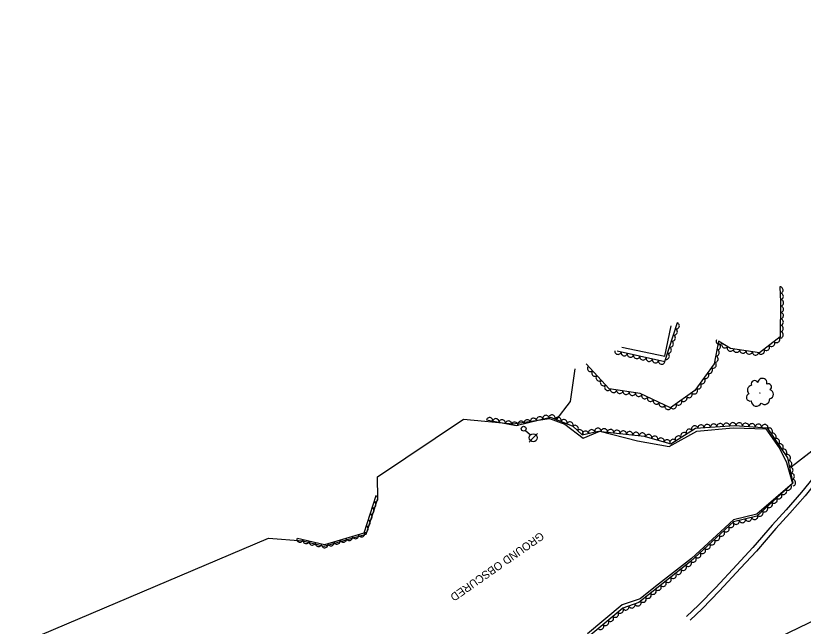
# Model space of a CAD drawing. Extents: x 1722896 to 1754269, y 648279 to 666297.
# Drawn here: x 1723621.5 to 1724113.3, y 664521.2 to 664902.6 of the extents above; entities that cross this region are included whole.
import ezdxf

# ---------------------------------------------------------------- set-up
doc = ezdxf.new("R2010")
doc.units = 0
for name, color, linetype in [('DESIGN - CENTERLINE - Proposed', 7, 'Continuous'), ('DESIGN - CENTERLINE - Proposed Text', 7, 'Continuous'), ('DESIGN - SCRATCH - User 1', 7, 'Continuous'), ('SURVEY - CENTERLINE - Preliminary', 7, 'Continuous'), ('SURVEY - CENTERLINE - Preliminary Text', 7, 'Continuous'), ('SURVEY - DTM - Breaklines', 7, 'Continuous'), ('SURVEY - VEGETATION - Features with Text', 7, 'Continuous')]:
    doc.layers.add(name, color=color, linetype=linetype)

msp = doc.modelspace()

# ---------------------------------------------------------------- linework, layer by layer
at = {"layer": 'DESIGN - CENTERLINE - Proposed'}
for points in [[(1724273.84, 664726.47), (1724258.5, 664715.78), (1724238.15, 664703.01), (1724220, 664690.73), (1724200.11, 664677.24), (1724179.59, 664664.67), (1724166.59, 664655.54), (1724151.47, 664644.92), (1724145.12, 664640.88), (1724139.39, 664634.1), (1724130.94, 664626.12), (1724122.18, 664617.34), (1724112.23, 664604.95), (1724102.71, 664594.02), (1724093.88, 664584.43), (1724081.77, 664570.4), (1724071.88, 664559.67), (1724058.71, 664545.5), (1724047.93, 664534.31), (1724040.41, 664527.26)], [(1724279.1, 664726.35), (1724260.75, 664713.56), (1724240.4, 664700.79), (1724222.25, 664688.52), (1724202.37, 664675.03), (1724181.84, 664662.46), (1724168.84, 664653.33), (1724153.72, 664642.7), (1724147.37, 664638.67), (1724141.65, 664631.89), (1724133.19, 664623.9), (1724124.43, 664615.13), (1724114.48, 664602.73), (1724104.96, 664591.81), (1724096.13, 664582.22), (1724084.02, 664568.19), (1724074.14, 664557.46), (1724060.96, 664543.28), (1724050.18, 664532.09), (1724042.67, 664525.05)]]:
    msp.add_lwpolyline(points, dxfattribs=at)
at = {"layer": 'DESIGN - CENTERLINE - Proposed Text'}
for points in [[(1724105.66, 664620.89), (1724149.56, 664654.64), (1724203.45, 664696.69), (1724251.99, 664732.46), (1724288.71, 664760.49), (1724304.32, 664767.21), (1724357.88, 664789.47), (1724411.6, 664811.84), (1724467.44, 664836.04), (1724528.61, 664861.58), (1724583.75, 664884.71), (1724626.01, 664902.56)], [(1724000.02, 664695.49), (1724026.87, 664689.9), (1724030.82, 664708.86)], [(1724105.66, 664620.89), (1724145.3, 664651.36)]]:
    msp.add_lwpolyline(points, dxfattribs=at)
at = {"layer": 'DESIGN - SCRATCH - User 1'}
msp.add_lwpolyline([(1724122.57, 664526.16), (1724091.92, 664511.24), (1724062.4, 664497.59), (1724031.5, 664483.84)], dxfattribs=at)
at = {"layer": 'SURVEY - CENTERLINE - Preliminary'}
for points in [[(1723621.54, 664509.22), (1723779.29, 664576.2), (1723800.75, 664574.58), (1723814.22, 664571.33), (1723840.37, 664578.82), (1723847.55, 664600.99), (1723847.4, 664614.53), (1723901.13, 664650.53), (1723932.15, 664647.59), (1723954.91, 664651.03), (1723964.4, 664647.44), (1723975.94, 664638.66), (1723986.23, 664643.1), (1724009.71, 664637.1), (1724029.66, 664633.44), (1724046.85, 664643.04), (1724069.49, 664645.12), (1724089.99, 664644.49)], [(1724089.99, 664644.49), (1724098.66, 664632.04), (1724102.86, 664623.56), (1724106.64, 664610.46), (1724084.34, 664591.21), (1724069.65, 664587.75), (1724043.55, 664563.45), (1724021.07, 664545.96), (1724011.52, 664538.4), (1724000.29, 664534.63), (1723978.66, 664516.56)]]:
    msp.add_lwpolyline(points, dxfattribs=at)
at = {"layer": 'SURVEY - CENTERLINE - Preliminary Text'}
msp.add_lwpolyline([(1723970.56, 664681.96), (1723967.78, 664661.56), (1723958.79, 664650)], dxfattribs=at)
at = {"layer": 'SURVEY - DTM - Breaklines'}
for p, q in [((1723939.79, 664643.59), (1723942.89, 664640.68)), ((1723944.71, 664638.97), (1723947.27, 664641.7)), ((1723944.71, 664638.97), (1723942.14, 664636.23))]:
    msp.add_line(p, q, dxfattribs=at)
for centre, radius in [((1723938.69, 664644.61), 1.5), ((1723944.71, 664638.97), 2.5)]:
    msp.add_circle(centre, radius, dxfattribs=at)
at = {"layer": 'SURVEY - VEGETATION - Features with Text'}
for points in [[(1724098.74, 664733.2), (1724099.13, 664723.8), (1724098.88, 664701.91), (1724085.93, 664692.1), (1724067.87, 664694.78), (1724060.42, 664699.36), (1724057.63, 664685.15), (1724045.59, 664668.4), (1724030.44, 664657.73), (1724011.39, 664666.52), (1723991.99, 664669.52), (1723977.75, 664685.19)], [(1724034.66, 664710.74), (1724026.68, 664686.48)], [(1724026.85, 664686.33), (1723996.99, 664693.03)], [(1723915.45, 664650.08), (1723934.03, 664646.67), (1723955.45, 664651.8), (1723969.43, 664646.19), (1723975.31, 664640.73), (1723985.16, 664643.12), (1724013.99, 664639.96), (1724030.5, 664635.17), (1724046.04, 664644.88), (1724070.58, 664646.61), (1724090.72, 664645.25), (1724103.45, 664626.42), (1724106.71, 664610.67), (1724084.28, 664590.07), (1724069.79, 664586.34), (1724042.87, 664561.57), (1724010.68, 664535.98), (1724000.66, 664532.6), (1723979.33, 664514.81)], [(1723846.44, 664602.75), (1723838.91, 664579.36), (1723814.27, 664572.04), (1723797.5, 664575.94)]]:
    msp.add_lwpolyline(points, dxfattribs=at)
msp.add_circle((1724086.22, 664667), 0.0997, dxfattribs=at)
for centre, radius, start, end in [((1724087.8, 664673.22), 2.85, 341.8001, 175.2198), ((1724081.49, 664668.72), 3.07, 99.7058, 226.5515), ((1724082.98, 664672.56), 2.17, 24.4188, 201.7379), ((1724091.5, 664670.64), 1.96, 301.7794, 120.5251), ((1724080.18, 664664.25), 2.38, 109.8647, 284.865), ((1724091.87, 664666.19), 2.86, 279.6633, 76.4522), ((1724084.03, 664661.92), 3.23, 179.6118, 335.4503), ((1724089.12, 664663.03), 3.25, 228.716, 6.2402)]:
    msp.add_arc(centre, radius, start, end, dxfattribs=at)
for centre, major_axis in [((1724098.82, 664731.2), (0.08, -2)), ((1724098.99, 664727.21), (0.08, -2)), ((1724099.12, 664723.21), (-0.02, -2)), ((1724099.08, 664719.21), (-0.02, -2)), ((1724099.03, 664715.21), (-0.02, -2)), ((1724034.04, 664708.84), (-0.62, -1.9)), ((1724098.98, 664711.21), (-0.02, -2)), ((1724032.79, 664705.04), (-0.62, -1.9)), ((1724098.94, 664707.21), (-0.02, -2)), ((1724031.54, 664701.24), (-0.62, -1.9)), ((1724096.73, 664700.28), (-1.59, -1.21)), ((1724098.89, 664703.21), (-0.02, -2)), ((1724029.04, 664693.64), (-0.62, -1.9)), ((1724030.29, 664697.44), (-0.62, -1.9)), ((1724060.89, 664699.07), (-1.7, 1.05)), ((1724059.76, 664695.98), (-0.39, -1.96)), ((1724064.3, 664696.97), (-1.7, 1.05)), ((1724067.71, 664694.88), (-1.7, 1.05)), ((1724090.36, 664695.45), (-1.59, -1.21)), ((1724093.54, 664697.86), (-1.59, -1.21)), ((1723997.57, 664692.9), (-1.95, 0.44)), ((1724001.48, 664692.02), (-1.95, 0.44)), ((1724005.38, 664691.15), (-1.95, 0.44)), ((1724009.28, 664690.27), (-1.95, 0.44)), ((1724027.79, 664689.84), (-0.62, -1.9)), ((1724058.99, 664692.05), (-0.39, -1.96)), ((1724071.64, 664694.22), (-1.98, 0.29)), ((1724075.59, 664693.63), (-1.98, 0.29)), ((1724079.55, 664693.04), (-1.98, 0.29)), ((1724083.51, 664692.46), (-1.98, 0.29)), ((1724087.17, 664693.03), (-1.59, -1.21)), ((1724013.19, 664689.4), (-1.95, 0.44)), ((1724017.09, 664688.52), (-1.95, 0.44)), ((1724020.99, 664687.65), (-1.95, 0.44)), ((1724024.89, 664686.77), (-1.95, 0.44)), ((1724057.07, 664684.37), (-1.17, -1.62)), ((1724058.22, 664688.13), (-0.39, -1.96)), ((1723980.42, 664682.25), (-1.35, 1.48)), ((1723983.11, 664679.29), (-1.35, 1.48)), ((1724054.73, 664681.12), (-1.17, -1.62)), ((1723985.8, 664676.33), (-1.35, 1.48)), ((1724050.06, 664674.62), (-1.17, -1.62)), ((1724052.4, 664677.87), (-1.17, -1.62)), ((1723988.49, 664673.37), (-1.35, 1.48)), ((1723991.18, 664670.41), (-1.35, 1.48)), ((1724047.73, 664671.37), (-1.17, -1.62)), ((1723994.76, 664669.09), (-1.98, 0.31)), ((1723998.71, 664668.48), (-1.98, 0.31)), ((1724002.66, 664667.87), (-1.98, 0.31)), ((1724006.62, 664667.26), (-1.98, 0.31)), ((1724010.57, 664666.65), (-1.98, 0.31)), ((1724014.27, 664665.19), (-1.82, 0.84)), ((1724042.05, 664665.9), (-1.64, -1.15)), ((1724045.32, 664668.21), (-1.64, -1.15)), ((1724017.9, 664663.52), (-1.82, 0.84)), ((1724021.53, 664661.84), (-1.82, 0.84)), ((1724035.5, 664661.3), (-1.64, -1.15)), ((1724038.77, 664663.6), (-1.64, -1.15)), ((1724025.17, 664660.17), (-1.82, 0.84)), ((1724028.8, 664658.49), (-1.82, 0.84)), ((1724032.23, 664659), (-1.64, -1.15)), ((1723917.42, 664649.72), (1.97, -0.36)), ((1723944.84, 664649.26), (1.95, 0.47)), ((1723948.73, 664650.19), (1.95, 0.47)), ((1723952.62, 664651.12), (1.95, 0.47)), ((1723956.46, 664651.39), (1.86, -0.74)), ((1723960.17, 664649.9), (1.86, -0.74)), ((1723921.35, 664649), (1.97, -0.36)), ((1723925.29, 664648.28), (1.97, -0.36)), ((1723929.22, 664647.55), (1.97, -0.36)), ((1723933.16, 664646.83), (1.97, -0.36)), ((1723937.06, 664647.4), (1.95, 0.47)), ((1723940.95, 664648.33), (1.95, 0.47)), ((1723963.88, 664648.42), (1.86, -0.74)), ((1723967.6, 664646.93), (1.86, -0.74)), ((1723970.91, 664644.82), (1.47, -1.36)), ((1724045.49, 664644.54), (1.7, 1.06)), ((1724049.38, 664645.11), (2, 0.14)), ((1724053.37, 664645.39), (2, 0.14)), ((1724057.36, 664645.68), (2, 0.14)), ((1724061.35, 664645.96), (2, 0.14)), ((1724065.34, 664646.24), (2, 0.14)), ((1724069.33, 664646.52), (2, 0.14)), ((1724073.32, 664646.42), (2, -0.13)), ((1724077.32, 664646.15), (2, -0.13)), ((1724081.31, 664645.88), (2, -0.13)), ((1724085.3, 664645.62), (2, -0.13)), ((1724089.29, 664645.35), (2, -0.13)), ((1723973.85, 664642.09), (1.47, -1.36)), ((1723977.26, 664641.21), (1.94, 0.47)), ((1723981.14, 664642.15), (1.94, 0.47)), ((1723985.03, 664643.09), (1.94, 0.47)), ((1723989, 664642.7), (1.99, -0.22)), ((1723992.98, 664642.27), (1.99, -0.22)), ((1723996.96, 664641.83), (1.99, -0.22)), ((1724000.93, 664641.39), (1.99, -0.22)), ((1724004.91, 664640.96), (1.99, -0.22)), ((1724008.88, 664640.52), (1.99, -0.22)), ((1724012.86, 664640.09), (1.99, -0.22)), ((1724038.7, 664640.3), (1.7, 1.06)), ((1724042.1, 664642.42), (1.7, 1.06)), ((1724092.16, 664643.12), (1.12, -1.66)), ((1724094.4, 664639.81), (1.12, -1.66)), ((1724016.74, 664639.16), (1.92, -0.56)), ((1724020.58, 664638.05), (1.92, -0.56)), ((1724024.42, 664636.93), (1.92, -0.56)), ((1724028.27, 664635.82), (1.92, -0.56)), ((1724031.92, 664636.06), (1.7, 1.06)), ((1724035.31, 664638.18), (1.7, 1.06)), ((1724096.64, 664636.5), (1.12, -1.66)), ((1724098.88, 664633.18), (1.12, -1.66)), ((1724101.12, 664629.87), (1.12, -1.66)), ((1724103.36, 664626.56), (1.12, -1.66)), ((1724104.23, 664622.66), (0.41, -1.96)), ((1724105.04, 664618.75), (0.41, -1.96)), ((1724105.85, 664614.83), (0.41, -1.96)), ((1724106.66, 664610.91), (0.41, -1.96)), ((1724103.94, 664608.13), (-1.47, -1.35)), ((1723845.83, 664600.85), (-0.61, -1.9)), ((1724098.05, 664602.72), (-1.47, -1.35)), ((1724101, 664605.43), (-1.47, -1.35)), ((1723844.6, 664597.04), (-0.61, -1.9)), ((1724092.16, 664597.31), (-1.47, -1.35)), ((1724095.11, 664600.02), (-1.47, -1.35)), ((1723843.37, 664593.23), (-0.61, -1.9)), ((1724086.27, 664591.9), (-1.47, -1.35)), ((1724089.21, 664594.6), (-1.47, -1.35)), ((1723840.92, 664585.62), (-0.61, -1.9)), ((1723842.15, 664589.43), (-0.61, -1.9)), ((1724075.27, 664587.76), (-1.94, -0.5)), ((1724079.15, 664588.75), (-1.94, -0.5)), ((1724083.02, 664589.75), (-1.94, -0.5)), ((1723839.7, 664581.81), (-0.61, -1.9)), ((1724065.13, 664582.05), (-1.47, -1.35)), ((1724068.07, 664584.76), (-1.47, -1.35)), ((1724071.4, 664586.76), (-1.94, -0.5)), ((1723833.71, 664577.81), (-1.92, -0.57)), ((1723837.54, 664578.95), (-1.92, -0.57)), ((1724059.24, 664576.64), (-1.47, -1.35)), ((1724062.18, 664579.35), (-1.47, -1.35)), ((1723798.96, 664575.6), (-1.95, 0.45)), ((1723802.85, 664574.7), (-1.95, 0.45)), ((1723806.75, 664573.79), (-1.95, 0.45)), ((1723810.65, 664572.88), (-1.95, 0.45)), ((1723814.54, 664572.12), (-1.92, -0.57)), ((1723818.37, 664573.26), (-1.92, -0.57)), ((1723822.21, 664574.4), (-1.92, -0.57)), ((1723826.04, 664575.54), (-1.92, -0.57)), ((1723829.87, 664576.67), (-1.92, -0.57)), ((1724053.35, 664571.22), (-1.47, -1.35)), ((1724056.3, 664573.93), (-1.47, -1.35)), ((1724050.41, 664568.51), (-1.47, -1.35)), ((1724044.52, 664563.09), (-1.47, -1.35)), ((1724047.47, 664565.8), (-1.47, -1.35)), ((1724038.37, 664557.99), (-1.57, -1.24)), ((1724041.5, 664560.48), (-1.57, -1.24)), ((1724032.1, 664553.01), (-1.57, -1.24)), ((1724035.24, 664555.5), (-1.57, -1.24)), ((1724025.84, 664548.03), (-1.57, -1.24)), ((1724028.97, 664550.52), (-1.57, -1.24)), ((1724019.58, 664543.06), (-1.57, -1.24)), ((1724022.71, 664545.55), (-1.57, -1.24)), ((1724013.32, 664538.08), (-1.57, -1.24)), ((1724016.45, 664540.57), (-1.57, -1.24)), ((1724002.5, 664533.23), (-1.9, -0.64)), ((1724006.29, 664534.5), (-1.9, -0.64)), ((1724010.08, 664535.78), (-1.9, -0.64)), ((1723996.01, 664528.72), (-1.54, -1.28)), ((1723999.08, 664531.29), (-1.54, -1.28)), ((1723989.87, 664523.6), (-1.54, -1.28)), ((1723992.94, 664526.16), (-1.54, -1.28)), ((1723986.8, 664521.04), (-1.54, -1.28))]:
    msp.add_ellipse(centre, major_axis=major_axis, ratio=0.940188, start_param=0, end_param=3.141593, dxfattribs=at)

# ---------------------------------------------------------------- texts
at = {"layer": 'SURVEY - CENTERLINE - Preliminary'}
msp.add_text('GROUND OBSCURED', height=5, rotation=214.9984, dxfattribs=at).set_placement((1723949.22, 664580.39))

doc.saveas('drawing.dxf')
